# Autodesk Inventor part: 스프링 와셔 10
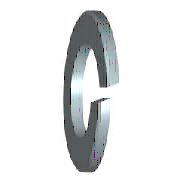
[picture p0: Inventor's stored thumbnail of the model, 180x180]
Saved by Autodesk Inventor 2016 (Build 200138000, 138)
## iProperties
Created: 2012-02
Part Number: 스프링 와셔 10
Material: 강철, 연강
Description: 스프링 잠금 와셔
Document SubType Name: Modeling
Standard: KS B 1324
Designer: mduedu
Standards Organization: KS
Language: ko-KR
Size Designation: 번호 2 - 10
Categories: <MemberInstance><Categories><Category DisplayName="조임쇠" InternalName="e4da775c-781d-43d5-af7c-5136215cf5a6" Mnemonic="FSTN"><Category DisplayName="와셔" InternalN
Density: 1 g/cm^3
Appearance: 강철
IsCustomPart: 1
Author: mduedu
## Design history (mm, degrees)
sketch "스케치1"
  geometry: C1 r 8.8 at (0, 0); C2 r 5.1 at (0, 0); 1 further point
  constraints: 2 centre point, 2 coincident
  dimensions: "d0" = 10.2 diameter of C2 (= SD1); "d1" = 17.6 diameter of C1 (= SD2)
extrude "본체" new body sketch "스케치1" distance "d2" = 2.5 (= SD); taper "d3" = 0 deg
sketch "스케치2"
  geometry: L1 (0, -5.1)-(0, 5.1) reference; L2 (2.5, 8.8)-(2.5, -8.8) reference; L3 (-1.2, 0)-(7.2, 0) reference; L4 (0, -0.5)-(2.5, 0.41); L5 (0, 0.5)-(2.5, 1.41)
  constraints: 4 end point, 4 point on line, 1 parallel
  dimensions: "d4" = 0.5 distance from line of L3 L4.start (= 0.2 x SD); "d5" = 0.5 distance from line of L3 L5.start (= 0.2 x SD); "d6" = 70 deg angle of L2 L4 (= FAWI)
extrude "절단부" cut sketch "스케치2" stored distance "d7" = 2.5 (= SD); taper "d8" = 0 deg
workaxis "Work Axis1"
workplane "Work Plane1"
body "Solid1"
other parameters: "SD1" = 10.2 [user parameter; used in 1 equation term], "SD2" = 17.6 [user parameter; used in 1 equation term], "SD" = 2.5 [user parameter; used in 4 equation terms], "FAWI" = 70 deg [user parameter; used in 1 equation term], "d9" = 0, "d10" = 0, "d11" = 0, "d12" = 0, "SDI" = 3.7 [user parameter]
